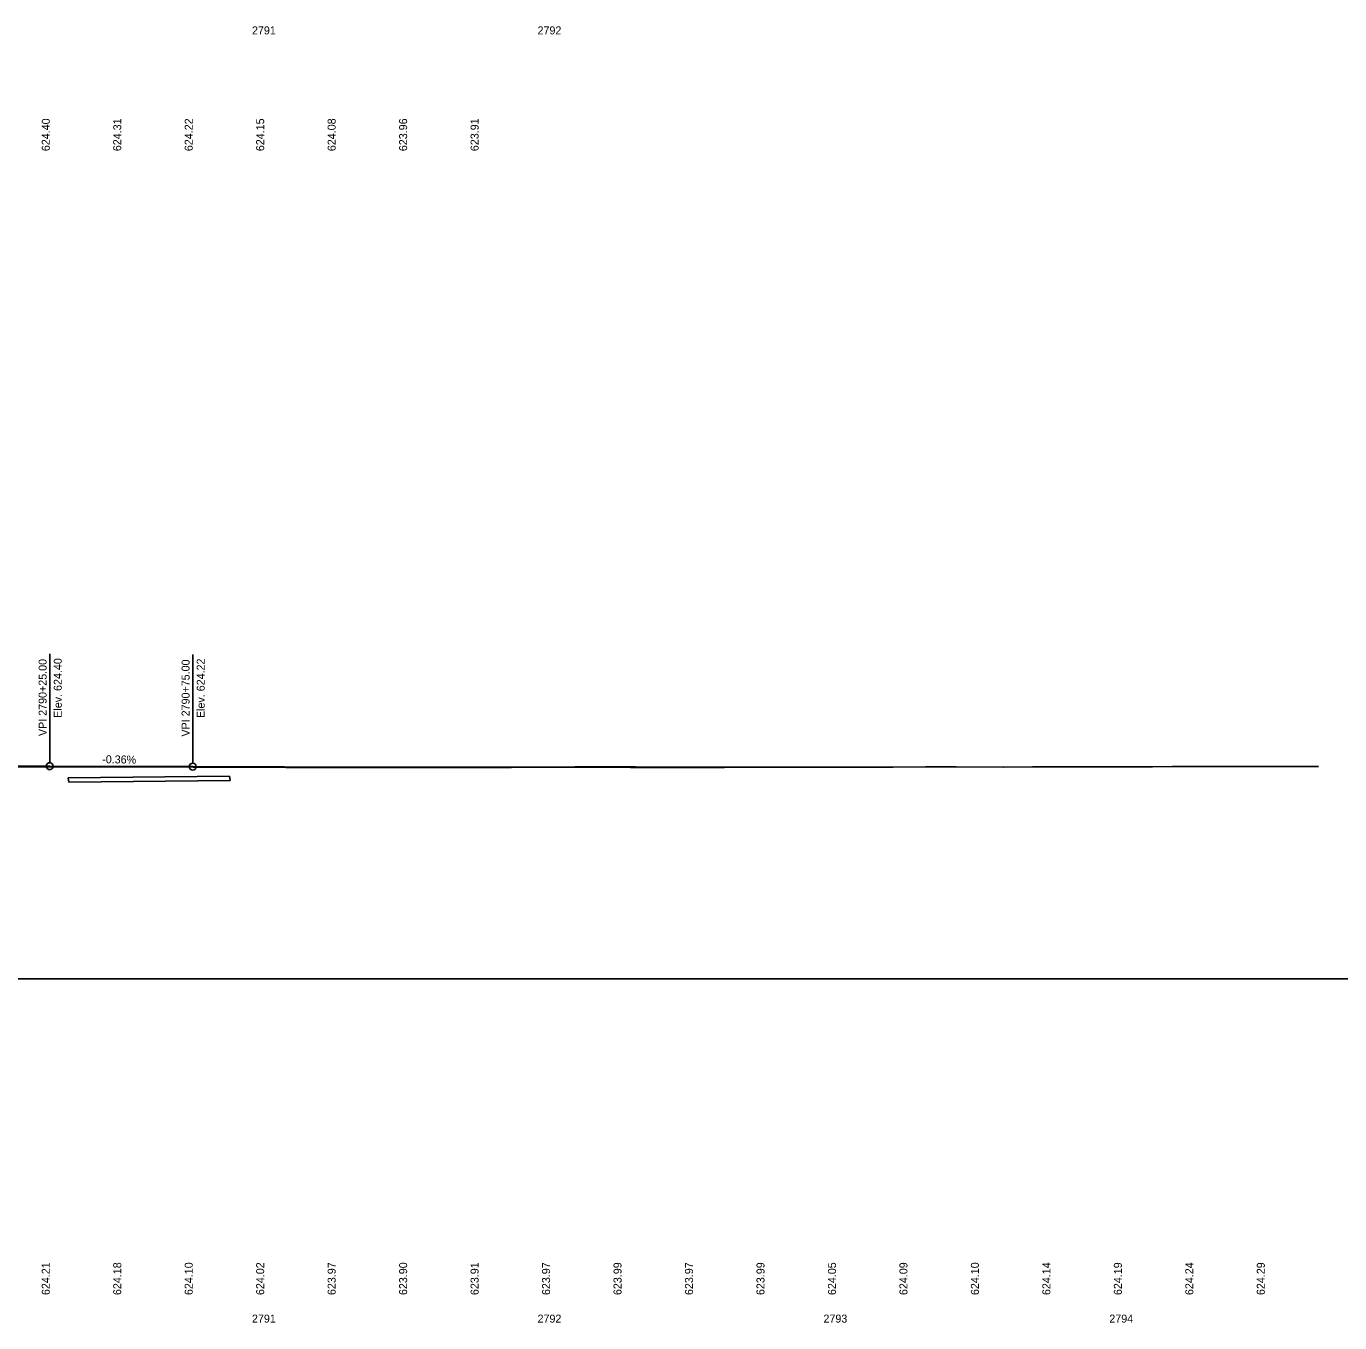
# Model space of a CAD drawing. Extents: x 2376379 to 2383101, y 559608 to 561720.
# Drawn here: x 2379582.4 to 2380041.8, y 559608.2 to 560061.6 of the extents above; entities that cross this region are included whole.
import ezdxf

# ---------------------------------------------------------------- set-up
doc = ezdxf.new("R2010")
doc.units = 0
for name, color, linetype in [('AP_P_Airside', 7, 'Continuous'), ('BR_X_SV_Shot_Marker', 7, 'Continuous'), ('DR_X_Erosion_Control', 7, 'Continuous'), ('DT_X_Island', 7, 'Continuous'), ('PV_X_Driveway', 7, 'Continuous'), ('SV_X_Text', 7, 'Continuous'), ('UT_X_Overhead_Electric', 7, 'Continuous')]:
    doc.layers.add(name, color=color, linetype=linetype)

msp = doc.modelspace()

# ---------------------------------------------------------------- linework, layer by layer
at = {"layer": 'AP_P_Airside'}
for p, q in [((2379590.62, 559804.07), (2379590.62, 559842.15)), ((2379640.62, 559803.89), (2379640.62, 559841.97))]:
    msp.add_line(p, q, dxfattribs=at)
for centre in [(2379590.62, 559802.86), (2379640.62, 559802.69)]:
    msp.add_circle(centre, 1.21, dxfattribs=at)
at = {"layer": 'DT_X_Island'}
for p, q in [((2379597.07, 559798.74), (2379653.52, 559799.31)), ((2379597.07, 559798.74), (2379597.31, 559797.24)), ((2379597.31, 559797.24), (2379653.76, 559797.81)), ((2379653.52, 559799.31), (2379653.76, 559797.81))]:
    msp.add_line(p, q, dxfattribs=at)
at = {"layer": 'PV_X_Driveway'}
msp.add_lwpolyline([(2379574.48, 559802.67), (2379598.49, 559802.67), (2379621.3, 559802.63), (2379621.85, 559802.64), (2379626.46, 559802.62), (2379640.83, 559802.56), (2379647.32, 559802.53), (2379647.58, 559802.53), (2379653.68, 559802.52), (2379672.76, 559802.46), (2379673.16, 559802.45), (2379698.79, 559802.42), (2379700.08, 559802.41), (2379722.31, 559802.35), (2379723.77, 559802.35), (2379749.27, 559802.38), (2379752.13, 559802.39), (2379774.32, 559802.46), (2379775.26, 559802.47), (2379793.8, 559802.45), (2379795.46, 559802.45), (2379825.85, 559802.43), (2379826.68, 559802.43), (2379843.27, 559802.46), (2379846.95, 559802.47), (2379847.18, 559802.47), (2379874.13, 559802.53), (2379874.5, 559802.53), (2379896.91, 559802.57), (2379897.5, 559802.57), (2379907.63, 559802.57), (2379924.19, 559802.56), (2379924.32, 559802.56), (2379934.36, 559802.59), (2379945.2, 559802.62), (2379948.67, 559802.62), (2379948.86, 559802.62), (2379975.92, 559802.67), (2379976.39, 559802.67), (2379983.21, 559802.69), (2379984.36, 559802.69), (2379999.16, 559802.72), (2379999.93, 559802.72), (2380024.78, 559802.77), (2380034.36, 559802.77)], dxfattribs=at)
at = {"layer": 'SV_X_Text'}
msp.add_line((2378765.62, 559728.46), (2380329.61, 559728.46), dxfattribs=at)
at = {"layer": 'UT_X_Overhead_Electric'}
for p, q in [((2379299.62, 559802.86), (2379590.62, 559802.86)), ((2379590.62, 559802.86), (2379640.62, 559802.69))]:
    msp.add_line(p, q, dxfattribs=at)
for points in [[(2379640.62, 559802.69), (2379647.58, 559802.66), (2379653.68, 559802.64), (2379672.76, 559802.58), (2379688.12, 559802.56)], [(2379688.12, 559802.56), (2379698.79, 559802.54), (2379700.08, 559802.54), (2379722.31, 559802.47), (2379723.77, 559802.47), (2379752.13, 559802.52), (2379774.32, 559802.59), (2379795.46, 559802.58), (2379825.85, 559802.55), (2379826.68, 559802.55), (2379833.12, 559802.56)], [(2379833.12, 559802.56), (2379843.27, 559802.56), (2379847.18, 559802.56), (2379874.13, 559802.56), (2379885.62, 559802.55)]]:
    msp.add_lwpolyline(points, dxfattribs=at)

# ---------------------------------------------------------------- texts
at = {"layer": 'AP_P_Airside'}
for s, rotation, p in [('VPI 2790+25.00', 90, (2379589.53, 559813.39)), ('Elev. 624.40', 90, (2379594.82, 559819.8)), ('VPI 2790+75.00', 90, (2379639.53, 559813.21)), ('Elev. 624.22', 90, (2379644.82, 559819.69)), ('-0.36%', 359.1874, (2379608.95, 559803.9))]:
    msp.add_text(s, height=2.8, rotation=rotation, dxfattribs=at).set_placement(p)
at = {"layer": 'BR_X_SV_Shot_Marker'}
for s, p in [('2791', (2379661.36, 560058.78)), ('2792', (2379761.24, 560058.78)), ('2791', (2379661.36, 559608.25)), ('2792', (2379761.24, 559608.25)), ('2793', (2379861.25, 559608.25)), ('2794', (2379961.24, 559608.25))]:
    msp.add_text(s, height=2.8, dxfattribs=at).set_placement(p)
for s, p in [('624.21', (2379590.62, 559617.89)), ('624.18', (2379615.62, 559617.89)), ('624.10', (2379640.62, 559617.89)), ('624.02', (2379665.62, 559617.89)), ('623.97', (2379690.62, 559617.89)), ('623.90', (2379715.62, 559617.89)), ('623.91', (2379740.62, 559617.89)), ('623.97', (2379765.62, 559617.89)), ('623.99', (2379790.62, 559617.89)), ('623.97', (2379815.62, 559617.89)), ('623.99', (2379840.62, 559617.89)), ('624.05', (2379865.62, 559617.89)), ('624.09', (2379890.62, 559617.89)), ('624.10', (2379915.62, 559617.89)), ('624.14', (2379940.62, 559617.89)), ('624.19', (2379965.62, 559617.89)), ('624.24', (2379990.62, 559617.89)), ('624.29', (2380015.62, 559617.89))]:
    msp.add_text(s, height=2.8, rotation=90, dxfattribs=at).set_placement(p)
at = {"layer": 'DR_X_Erosion_Control'}
for s, p in [('624.40', (2379590.62, 560017.95)), ('624.31', (2379615.62, 560017.95)), ('624.22', (2379640.62, 560017.95)), ('624.15', (2379665.62, 560017.95)), ('624.08', (2379690.62, 560017.95)), ('623.96', (2379715.62, 560017.95)), ('623.91', (2379740.62, 560017.95))]:
    msp.add_text(s, height=2.8, rotation=90, dxfattribs=at).set_placement(p)

doc.saveas('drawing.dxf')
